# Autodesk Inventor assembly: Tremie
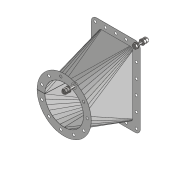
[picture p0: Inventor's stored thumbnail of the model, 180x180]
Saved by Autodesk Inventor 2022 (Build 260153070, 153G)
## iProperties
Created: 2021-07
Part Number: Tremie
Document SubType Name: Construction soudée
Designer: Fabian
Weld Material: Aluminium 6061, soudé
Author: Fabian
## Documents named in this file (5)
- C:\Users\Fabian\Google Drive\01_Giup\01_Clients\07_ENI\Manuscrit\Fichiers_exercice\Chapitre_06\Exercice_reseau\Exdercice_reseau.iam
- C:\Users\Fabian\Google Drive\01_Giup\01_Clients\07_ENI\Manuscrit\Fichiers_exercice\Chapitre_06\Exercice_reseau\Bride_rect.ipt
- C:\Users\Fabian\Google Drive\01_Giup\01_Clients\07_ENI\Manuscrit\Fichiers_exercice\Chapitre_06\Exercice_reseau\Tremi.ipt
- C:\Users\Fabian\Google Drive\01_Giup\01_Clients\07_ENI\Manuscrit\Fichiers_exercice\Chapitre_06\Exercice_reseau\Bride_circ.ipt
- C:\Users\Fabian\Google Drive\01_Giup\01_Clients\07_ENI\Manuscrit\Fichiers_exercice\Chapitre_06\Exercice_reseau\Attache.iam
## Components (5 placed, 4 different names)
1. Bride_rect:1 — Logement:5
2. Tremi:1
3. Bride_circ:1 — Logement:4
4. Attache:2 [sub-assembly] — Logement:4
5. Attache:1 [sub-assembly] — Logement:5
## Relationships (2: Insert 2)
- Logement:4 [Insert]: Bride_circ:1 ↔ Attache:2
- Logement:5 [Insert]: Bride_rect:1 ↔ Attache:1
